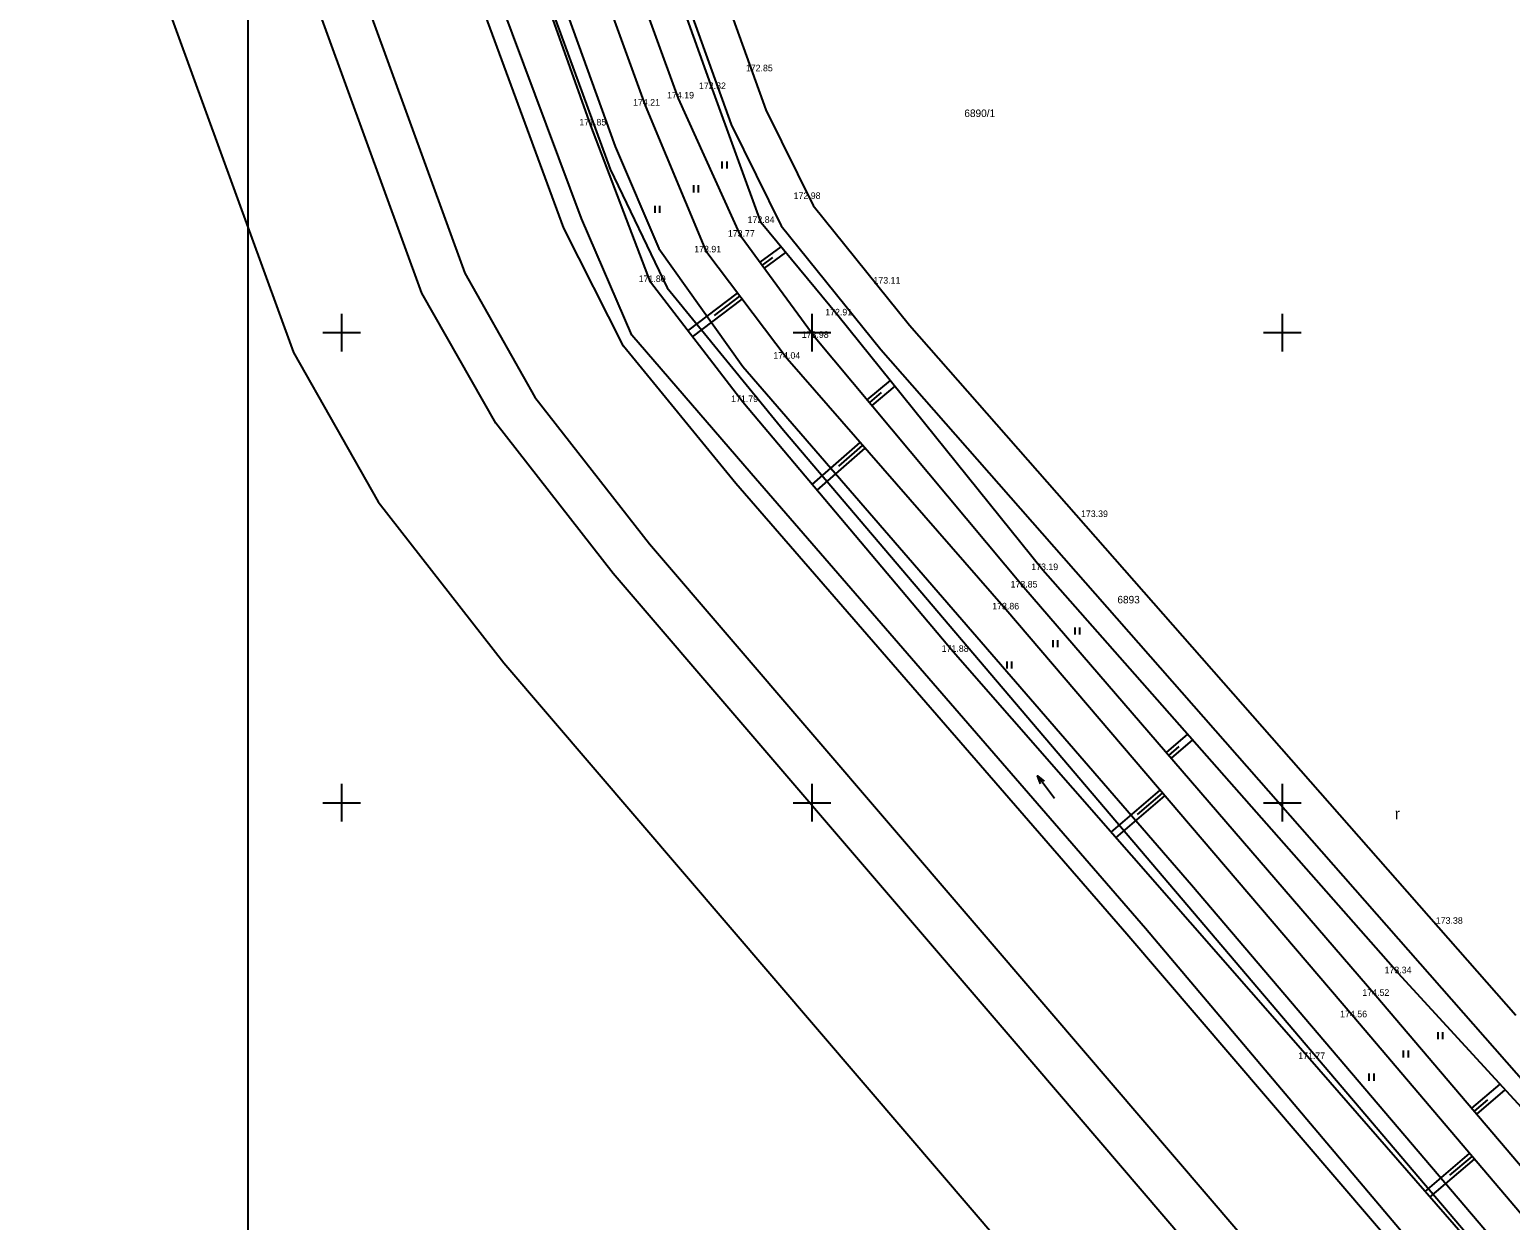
# Model space of a CAD drawing. Extents: x -612546 to -611926, y -1201932 to -1200444.
# Drawn here: x -612383.2 to -612225.8, y -1200994.4 to -1200867.8 of the extents above; entities that cross this region are included whole.
import ezdxf

# ---------------------------------------------------------------- set-up
doc = ezdxf.new("R2010")
doc.units = 0
for name, color, linetype in [('14 hrana pata svahu', 7, 'Continuous'), ('15 šrafy', 7, 'Continuous'), ('61 legenda křížky', 7, 'Continuous'), ('Hranice parcel', 7, 'Continuous'), ('Parcelní čísla', 7, 'Continuous'), ('Vnitřní kresba', 7, 'Continuous'), ('Vrstva 36', 7, 'Continuous'), ('Vrstva 45', 7, 'Continuous'), ('Vrstva 63', 7, 'Continuous'), ('výška bodu', 7, 'Continuous')]:
    doc.layers.add(name, color=color, linetype=linetype)

msp = doc.modelspace()

# ---------------------------------------------------------------- linework, layer by layer
at = {"layer": '14 hrana pata svahu'}
for points in [[(-612115.84, -1201111.42), (-612142.3, -1201080.92), (-612162.58, -1201054.92), (-612187.22, -1201025.94), (-612211.45, -1200996.73), (-612237.71, -1200968.13), (-612275.47, -1200925.26), (-612297.25, -1200898.18), (-612305.42, -1200888.34), (-612310.59, -1200874.11), (-612323.74, -1200837.38), (-612336.44, -1200801.43), (-612350.12, -1200764.09), (-612361.57, -1200731.35), (-612377.95, -1200692.77), (-612388.38, -1200663.69), (-612401.66, -1200625.89), (-612414.44, -1200590.59), (-612427.78, -1200553.92), (-612436.33, -1200532.1), (-612442.76, -1200519.02), (-612455.83, -1200502.43), (-612463.71, -1200487.36), (-612471.87, -1200478.15)], [(-612103.83, -1201136.8), (-612121.3, -1201116.23), (-612147.17, -1201085.43), (-612168.95, -1201059.31), (-612192.84, -1201031.05), (-612217.78, -1201001.78), (-612242.41, -1200972.81), (-612279.4, -1200929.44), (-612302.66, -1200902.78), (-612311.18, -1200891.48), (-612317.69, -1200875.87), (-612330.64, -1200840.25), (-612343.46, -1200803.61), (-612356.83, -1200766.41), (-612369.51, -1200733.46), (-612383.93, -1200694.82), (-612394.68, -1200665.1), (-612407.78, -1200627.56), (-612420.74, -1200592.57), (-612433.93, -1200555.79), (-612441.34, -1200534.1), (-612447.31, -1200522.04), (-612459.97, -1200505.78), (-612472.95, -1200489.44)], [(-612100.62, -1201134.15), (-612118.63, -1201113.83), (-612144.42, -1201082.96), (-612165.7, -1201057.43), (-612190.2, -1201028.76), (-612215.18, -1200999.78), (-612240.07, -1200970.53), (-612277.47, -1200927.11), (-612299.67, -1200900.56), (-612307.52, -1200889.81), (-612314.18, -1200875.11), (-612327.34, -1200838.97)], [(-612083.4, -1201170.96), (-612107.88, -1201140.83), (-612125.72, -1201119.76), (-612151.16, -1201088.66), (-612173.22, -1201063.29), (-612197.5, -1201034.61), (-612222.4, -1201005.63), (-612247.09, -1200977.25), (-612284.99, -1200933.95), (-612307.37, -1200907.39), (-612317.17, -1200894.63), (-612323.51, -1200877.98), (-612336.33, -1200841.94)]]:
    msp.add_lwpolyline(points, dxfattribs=at)
at = {"layer": '15 šrafy'}
for p, q in [((-612303.32, -1200890.87), (-612305.56, -1200892.5)), ((-612302.81, -1200891.48), (-612305.09, -1200893.14)), ((-612304.21, -1200892.01), (-612305.32, -1200892.82)), ((-612313.19, -1200899.81), (-612307.91, -1200895.82)), ((-612310.36, -1200898.17), (-612307.67, -1200896.14)), ((-612312.71, -1200900.44), (-612307.42, -1200896.46)), ((-612291.7, -1200905.09), (-612294.16, -1200907.15)), ((-612291.19, -1200905.71), (-612293.65, -1200907.76)), ((-612292.64, -1200906.39), (-612293.9, -1200907.45)), ((-612299.99, -1200916.15), (-612294.88, -1200911.7)), ((-612297.15, -1200914.21), (-612294.62, -1200912)), ((-612299.47, -1200916.76), (-612294.36, -1200912.3)), ((-612260.1, -1200942.71), (-612262.36, -1200944.66)), ((-612259.57, -1200943.31), (-612261.84, -1200945.26)), ((-612261, -1200944.01), (-612262.1, -1200944.96)), ((-612268.22, -1200953.11), (-612263, -1200948.67)), ((-612267.69, -1200953.72), (-612262.48, -1200949.27)), ((-612265.42, -1200951.25), (-612262.74, -1200948.97)), ((-612226.88, -1200979.93), (-612229.89, -1200982.49)), ((-612226.34, -1200980.52), (-612229.37, -1200983.1)), ((-612228.19, -1200981.57), (-612229.63, -1200982.8)), ((-612234.84, -1200991.33), (-612230.1, -1200987.29)), ((-612232.19, -1200989.59), (-612229.84, -1200987.6)), ((-612234.32, -1200991.93), (-612229.58, -1200987.9))]:
    msp.add_line(p, q, dxfattribs=at)
at = {"layer": '61 legenda křížky'}
for p, q in [((-612350, -1200902), (-612350, -1200898)), ((-612300, -1200902), (-612300, -1200898)), ((-612250, -1200902), (-612250, -1200898)), ((-612352, -1200900), (-612348, -1200900)), ((-612302, -1200900), (-612298, -1200900)), ((-612252, -1200900), (-612248, -1200900)), ((-612350, -1200952), (-612350, -1200948)), ((-612300, -1200952), (-612300, -1200948)), ((-612250, -1200952), (-612250, -1200948)), ((-612352, -1200950), (-612348, -1200950)), ((-612302, -1200950), (-612298, -1200950)), ((-612252, -1200950), (-612248, -1200950))]:
    msp.add_line(p, q, dxfattribs=at)
at = {"layer": 'Hranice parcel'}
for points in [[(-612492.54, -1200475.45), (-612489.15, -1200479.9), (-612487.29, -1200482.34), (-612470.55, -1200499.86), (-612454.58, -1200517.89), (-612449.12, -1200526.98), (-612444.88, -1200537.01), (-612400.71, -1200658.68), (-612382.76, -1200708.97), (-612320.94, -1200880.21), (-612316.28, -1200891.06), (-612307.37, -1200903.62), (-612259.67, -1200958.71), (-612214.29, -1201012.03), (-612172.62, -1201060.98), (-612120.7, -1201123.05), (-612073.85, -1201178.4), (-612068.4, -1201184.83), (-612055.42, -1201199.11), (-612044.78, -1201213.9), (-612040.42, -1201224.33), (-612036.87, -1201232.26)], [(-612053.63, -1201234.04), (-612049.72, -1201229.74), (-612051.31, -1201220.57), (-612058.28, -1201208.42), (-612073.89, -1201189.58), (-612079.31, -1201183.16), (-612173.25, -1201072.99), (-612266.53, -1200963.98), (-612308.11, -1200916.05), (-612320.05, -1200901.46), (-612326.37, -1200888.91), (-612352.76, -1200817.26), (-612383.45, -1200732.24), (-612424.46, -1200618.96), (-612450.75, -1200547.77), (-612455.75, -1200534.91), (-612462.05, -1200524.68), (-612490.01, -1200492.58), (-612497.19, -1200482.99)], [(-612504.85, -1200495.41), (-612492.66, -1200506.93), (-612476.27, -1200525), (-612462.43, -1200549.41), (-612435.01, -1200623.69), (-612394.62, -1200736.44), (-612362.83, -1200822.52), (-612336.91, -1200893.7), (-612329.46, -1200906.86), (-612317.29, -1200922.46), (-612274.72, -1200972.15), (-612181.97, -1201080.59), (-612092.56, -1201185.28), (-612096.16, -1201188.77)], [(-612098.55, -1201185.97), (-612185.77, -1201083.84), (-612278.52, -1200975.4), (-612321.16, -1200925.63), (-612333.63, -1200909.64), (-612341.47, -1200895.8), (-612367.52, -1200824.24), (-612399.32, -1200738.15), (-612439.71, -1200625.4), (-612466.98, -1200551.52), (-612480.35, -1200527.95), (-612496.23, -1200510.43), (-612507.54, -1200499.75)], [(-612424.14, -1200544.19), (-612385.56, -1200652.97), (-612376.97, -1200665.68), (-612365.31, -1200671.92), (-612359.59, -1200681.01), (-612363.6, -1200702.67), (-612362.5, -1200716.42), (-612304.9, -1200876.31), (-612299.88, -1200886.48), (-612289.63, -1200899.21), (-612225.19, -1200972.6)], [(-612480.63, -1200557.86), (-612453.81, -1200630.53), (-612413.42, -1200743.28), (-612381.61, -1200829.41), (-612355.13, -1200902.11), (-612346.14, -1200918), (-612332.78, -1200935.12), (-612289.91, -1200985.15), (-612197.17, -1201093.58), (-612109.96, -1201195.71)], [(-612367.63, -1200702.46), (-612366.44, -1200717.27), (-612308.59, -1200877.88), (-612303.27, -1200888.65), (-612292.69, -1200901.79), (-612203.37, -1201003.51), (-612163.72, -1201050.75), (-612139.89, -1201080.24), (-612084.23, -1201147.54), (-612068.31, -1201163.86)]]:
    msp.add_lwpolyline(points, dxfattribs=at)
at = {"layer": 'Vnitřní kresba'}
for p, q in [((-612380.36, -1200721.61), (-612321.45, -1200882.64)), ((-612321.45, -1200882.64), (-612315.39, -1200895.25)), ((-612315.39, -1200895.25), (-612303.02, -1200910.37)), ((-612303.02, -1200910.37), (-612174.91, -1201061.11))]:
    msp.add_line(p, q, dxfattribs=at)
msp.add_lwpolyline([(-612077.99, -1201182.01), (-612172.2, -1201072.72), (-612264.55, -1200963.36), (-612306.48, -1200914.97), (-612319.15, -1200900.26), (-612324.5, -1200887.86), (-612350.35, -1200818.69), (-612381.6, -1200731.97), (-612422.84, -1200618.87), (-612449.81, -1200544.11), (-612465.28, -1200517.45), (-612482.79, -1200495.64), (-612497.19, -1200482.99)], dxfattribs=at)
at = {"layer": 'Vrstva 36'}
for p, q in [((-612309.54, -1200882.57), (-612309.54, -1200881.82)), ((-612309.04, -1200882.57), (-612309.04, -1200881.82)), ((-612312.56, -1200885.09), (-612312.56, -1200884.34)), ((-612312.06, -1200885.09), (-612312.06, -1200884.34)), ((-612316.69, -1200887.28), (-612316.69, -1200886.53)), ((-612316.19, -1200887.28), (-612316.19, -1200886.53)), ((-612272.03, -1200932.12), (-612272.03, -1200931.37)), ((-612271.53, -1200932.12), (-612271.53, -1200931.37)), ((-612274.38, -1200933.46), (-612274.38, -1200932.71)), ((-612273.88, -1200933.46), (-612273.88, -1200932.71)), ((-612279.26, -1200935.73), (-612279.26, -1200934.98)), ((-612278.76, -1200935.73), (-612278.76, -1200934.98)), ((-612233.45, -1200975.13), (-612233.45, -1200974.38)), ((-612232.95, -1200975.13), (-612232.95, -1200974.38)), ((-612237.11, -1200977.1), (-612237.11, -1200976.35)), ((-612236.61, -1200977.1), (-612236.61, -1200976.35)), ((-612240.76, -1200979.55), (-612240.76, -1200978.8)), ((-612240.26, -1200979.55), (-612240.26, -1200978.8))]:
    msp.add_line(p, q, dxfattribs=at)
at = {"layer": 'Vrstva 45'}
msp.add_line((-612274.23, -1200949.53), (-612276.04, -1200947.14), dxfattribs=at)
msp.add_lwpolyline([(-612275.7, -1200947.98), (-612276.04, -1200947.14), (-612275.33, -1200947.7)], dxfattribs=at)
at = {"layer": 'Vrstva 63'}
msp.add_line((-612359.93, -1201251.26), (-612359.93, -1200831.26), dxfattribs=at)

# ---------------------------------------------------------------- texts
at = {"layer": 'Parcelní čísla'}
for s, p in [('6890/1', (-612283.81, -1200877.08)), ('6893', (-612267.54, -1200928.8))]:
    msp.add_text(s, height=0.8, dxfattribs=at).set_placement(p)
at = {"layer": 'Vrstva 36'}
msp.add_text('r', height=1.2, dxfattribs=at).set_placement((-612238.05, -1200951.77))
at = {"layer": 'výška bodu'}
for s, p in [('172.85', (-612307.04, -1200872.22)), ('172.82', (-612312.02, -1200874.11)), ('174.21', (-612319.03, -1200875.87)), ('174.19', (-612315.41, -1200875.11)), ('171.85', (-612324.74, -1200877.98)), ('172.98', (-612301.96, -1200885.79)), ('172.84', (-612306.85, -1200888.34)), ('173.77', (-612308.95, -1200889.81)), ('173.91', (-612312.53, -1200891.48)), ('171.80', (-612318.43, -1200894.63)), ('173.11', (-612293.47, -1200894.79)), ('172.91', (-612298.6, -1200898.18)), ('173.98', (-612301.1, -1200900.56)), ('174.04', (-612304.12, -1200902.78)), ('171.79', (-612308.6, -1200907.39)), ('173.39', (-612271.41, -1200919.62)), ('173.19', (-612276.7, -1200925.26)), ('173.85', (-612278.9, -1200927.11)), ('173.86', (-612280.85, -1200929.44)), ('171.88', (-612286.22, -1200933.95)), ('173.38', (-612233.69, -1200962.87)), ('173.34', (-612239.14, -1200968.13)), ('174.52', (-612241.5, -1200970.53)), ('174.56', (-612243.86, -1200972.81)), ('171.77', (-612248.32, -1200977.25))]:
    msp.add_text(s, height=0.7, dxfattribs=at).set_placement(p)

doc.saveas('drawing.dxf')
